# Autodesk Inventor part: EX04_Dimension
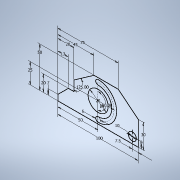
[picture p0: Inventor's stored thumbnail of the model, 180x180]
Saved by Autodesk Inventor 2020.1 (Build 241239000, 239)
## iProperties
Created: 2019-10
Part Number: EX04_Dimension
Material: Generic
Document SubType Name: Modeling
Designer: Synergysoft Dell02
Density: 1 g/cm^3
Appearance: Default
Author: Synergysoft Dell02
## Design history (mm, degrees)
sketch "Sketch1"
  geometry: L1 (0, 0)-(0, 7); L2 (0, 7)-(13, 20); L3 (13, 20)-(20, 20); L4 (20, 20)-(20, 32.495); L5 (20, 32.495)-(45, 50); L6 (45, 50)-(75, 50); L7 (75, 50)-(100, 30); L8 (100, 30)-(100, 0); L9 (100, 0)-(0, 0); L10 (50, 25)-(50, 5); L11 (50, 25)-(50, 45); L12 (92.5, 15.096)-(92.5, 0.904); L13 (85.875, 8)-(99.125, 8); C1 r 12.5 at (50, 25); C2 r 5 at (92.5, 8); A1 r 20 centre (50, 25) between (50, 5) and (50, 45); A2 r 23 centre (50, 25) between (50, 2) and (50, 48); A3 r 17 centre (50, 25) between (50, 8) and (50, 42); A4 r 3 centre (50, 5) between (50, 8) and (50, 2); A5 r 3 centre (50, 45) between (50, 48) and (50, 42); 1 further point
  constraints: 26 end point, 10 point on circle, 7 centre point, 4 tangent, 2 coincident, 2 horizontal, 2 midpoint, 2 parallel, 2 perpendicular, 2 vertical, 1 vertical alignment
  dimensions: "d0" = 7 distance of L1.start L1.end; "d1" = 50 distance between parallel lines of L6 L9; "d2" = 100 distance between parallel lines of L8 L1; "d3" = 20 distance between parallel lines of L3 L9; "d4" = 13 distance from line of L2.end L1; "d5" = 20 distance between parallel lines of L4 L1; "d6" = 45 horizontal distance of L5.end L1.start; "d7" = 75 horizontal distance of L6.end L1.start; "d8" = 30 distance of L7.end L8.end; "d9" = 125 deg angle of L5 L4; "d10" = 25 diameter of C1; "d11" = 50 distance from line of C1.centre L1; "d12" = 25 distance from line of C1.centre L9; "d13" = 20 radius of A1; "d14" = 180 deg angle of L11 L10; "d15" = 6 diameter of A4; "d16" = 10 diameter of C2; "d17" = 8 distance from line of L9 C2.centre; "d18" = 7.5 distance from line of C2.centre L8
